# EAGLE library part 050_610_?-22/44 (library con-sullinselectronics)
.050 DIP EDGE CARD CONNECTOR .050 [1.27mm] CONTACT CENTERS .610" INSULATEOR HEIGHT Source: .050 DIP EDGE CARD.pdf
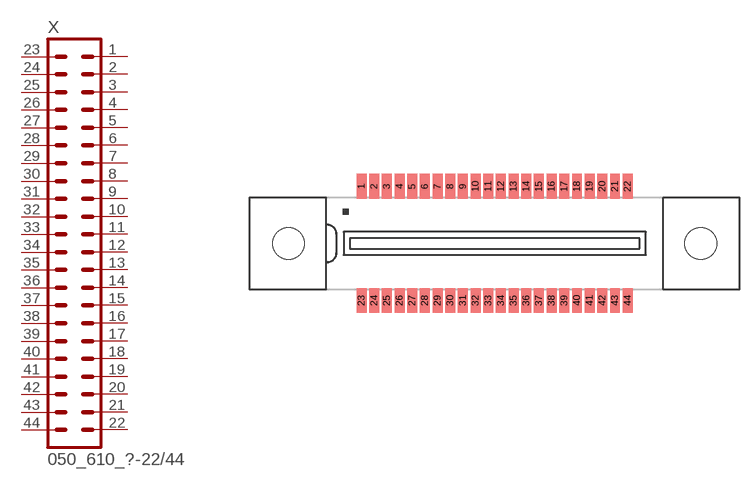
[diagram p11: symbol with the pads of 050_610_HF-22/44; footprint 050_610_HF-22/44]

Designator prefix X

## 050_610_HF-22/44 (OC_FARNELL: unknown; OC_NEWARK: unknown)  [050_610_HF-22/44]
1  1  pas
2  2  pas
3  3  pas
4  4  pas
5  5  pas
6  6  pas
7  7  pas
8  8  pas
9  9  pas
10  10  pas
11  11  pas
12  12  pas
13  13  pas
14  14  pas
15  15  pas
16  16  pas
17  17  pas
18  18  pas
19  19  pas
20  20  pas
21  21  pas
22  22  pas
23  23  pas
24  24  pas
25  25  pas
26  26  pas
27  27  pas
28  28  pas
29  29  pas
30  30  pas
31  31  pas
32  32  pas
33  33  pas
34  34  pas
35  35  pas
36  36  pas
37  37  pas
38  38  pas
39  39  pas
40  40  pas
41  41  pas
42  42  pas
43  43  pas
44  44  pas

## Footprint 050_610_HF-22/44 (pad centres in mm)
.050 DIP EDGE CARD CONNECTOR SURFACE MOUNT .050 [1.27mm] CONTACT CENTERS .610" INSULATEOR HEIGHT Source: .050 DIP EDGE CARD.pdf
smd 1 x 2.5: 1 -13.335,5.715; 2 -12.065,5.715; 3 -10.795,5.715; 4 -9.525,5.715; 5 -8.255,5.715; 6 -6.985,5.715; 7 -5.715,5.715; 8 -4.445,5.715; 9 -3.175,5.715; 10 -1.905,5.715; 11 -0.635,5.715; 12 0.635,5.715; 13 1.905,5.715; 14 3.175,5.715; 15 4.445,5.715; 16 5.715,5.715; 17 6.985,5.715; 18 8.255,5.715; 19 9.525,5.715; 20 10.795,5.715; 21 12.065,5.715; 22 13.335,5.715; 23 -13.335,-5.715; 24 -12.065,-5.715; 25 -10.795,-5.715; 26 -9.525,-5.715; 27 -8.255,-5.715; 28 -6.985,-5.715; 29 -5.715,-5.715; 30 -4.445,-5.715; 31 -3.175,-5.715; 32 -1.905,-5.715; 33 -0.635,-5.715; 34 0.635,-5.715; 35 1.905,-5.715; 36 3.175,-5.715; 37 4.445,-5.715; 38 5.715,-5.715; 39 6.985,-5.715; 40 8.255,-5.715; 41 9.525,-5.715; 42 10.795,-5.715; 43 12.065,-5.715; 44 13.335,-5.715
hole 3.18 at -20.65,0
hole 3.18 at 20.65,0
